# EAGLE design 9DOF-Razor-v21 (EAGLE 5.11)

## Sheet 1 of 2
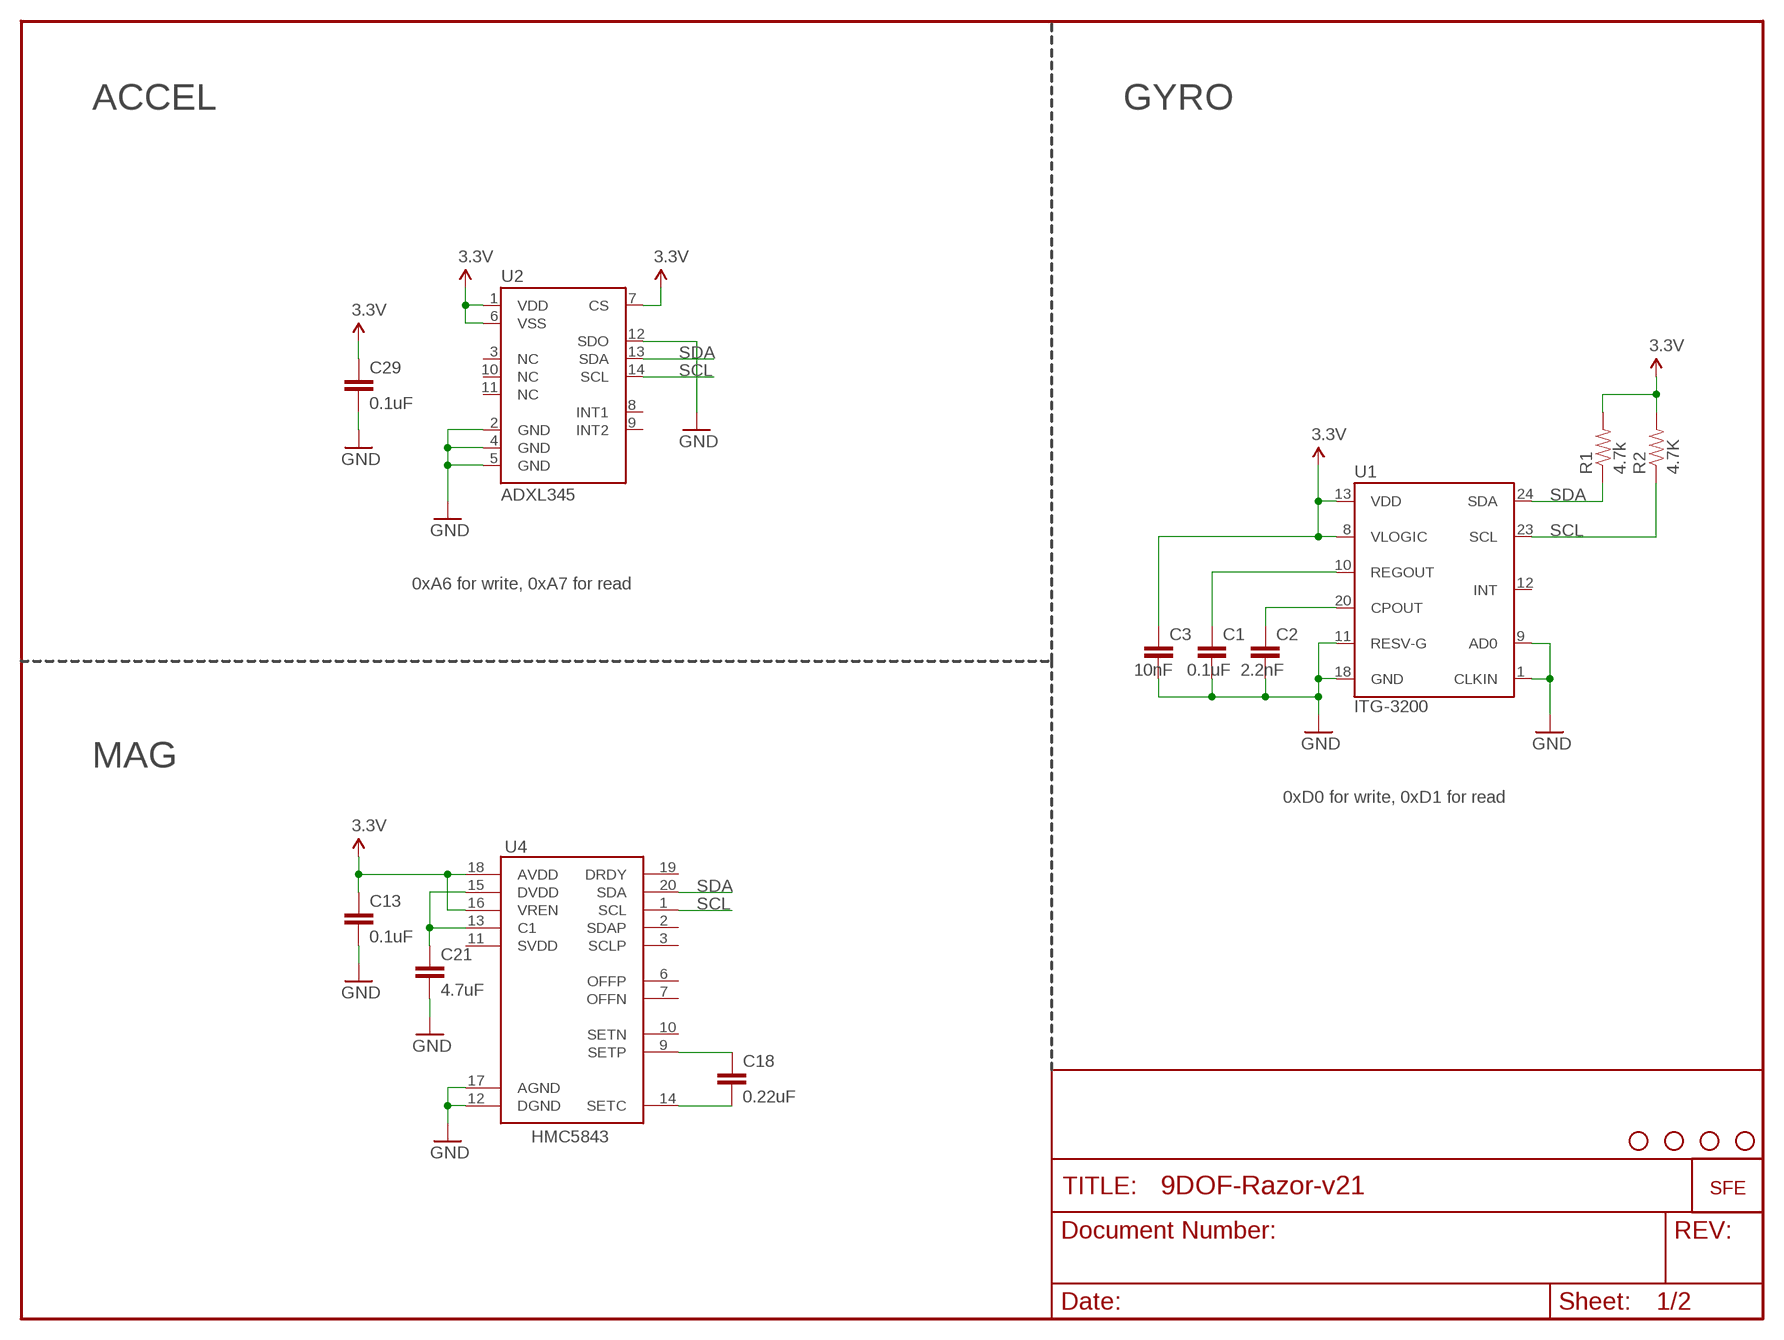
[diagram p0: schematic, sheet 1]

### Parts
C1  0.1uF  CAP0402-CAP  [0402-CAP]
C2  2.2nF  CAP0402-CAP  [0402-CAP]
C3  10nF  CAP0402-CAP  [0402-CAP]
C13  0.1uF  CAP0402-CAP  [0402-CAP]
C18  0.22uF  CAP0402-CAP  [0402-CAP]
C21  4.7uF  CAP0402-CAP  [0402-CAP]
C29  0.1uF  CAP0402-CAP  [0402-CAP]
JP2  STAND-OFF  [STAND-OFF]
JP3  LOGO-SFENEW  [SFE-NEW-WEBLOGO]
JP4  STAND-OFF  [STAND-OFF]
JP5  STAND-OFF  [STAND-OFF]
JP6  STAND-OFF  [STAND-OFF]
R1  4.7k  RESISTOR0402-RES  [0402-RES]
R2  4.7K  RESISTOR0402-RES  [0402-RES]
U1  ITG-3200  [QFN-24]
U2  ADXL345  [LGA14]
U4  HMC5843  HMC5843SMD  [LPCC20]

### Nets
3.3V: C3.1 C13.1 C29.1 R1.2 R2.2 U1.8(VLOGIC) U1.13(VDD) U2.1(VDD) U2.6(VSS) U2.7(CS) U4.16(VREN) U4.18(AVDD) ; also sheet 2
GND: C1.2 C2.2 C3.2 C13.2 C21.2 C29.2 U1.1(CLKIN) U1.9(AD0) U1.11(RESV-G) U1.18(GND) U2.2(GND) U2.4(GND) U2.5(GND) U2.12(SDO) U4.12(DGND) U4.17(AGND) ; also sheet 2
N$3: C1.1 U1.10(REGOUT)
N$4: C2.1 U1.20(CPOUT)
N$5: C21.1 U4.13(C1) U4.15(DVDD)
N$7: C18.1 U4.14(SETC)
N$11: C18.2 U4.9(SETP)
SCL: R2.1 U1.23(SCL) U2.14(SCL) U4.1(SCL) ; also sheet 2
SDA: R1.1 U1.24(SDA) U2.13(SDA) U4.20(SDA) ; also sheet 2
Unconnected: U1.12(INT) U2.3(NC) U2.8(INT1) U2.9(INT2) U2.10(NC) U2.11(NC) U4.2(SDAP) U4.3(SCLP) U4.6(OFFP) U4.7(OFFN) U4.10(SETN) U4.11(SVDD) U4.19(DRDY)

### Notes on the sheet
- ACCEL | GYRO
- 0xA6 for write, 0xA7 for read
- MAG
- 0xD0 for write, 0xD1 for read

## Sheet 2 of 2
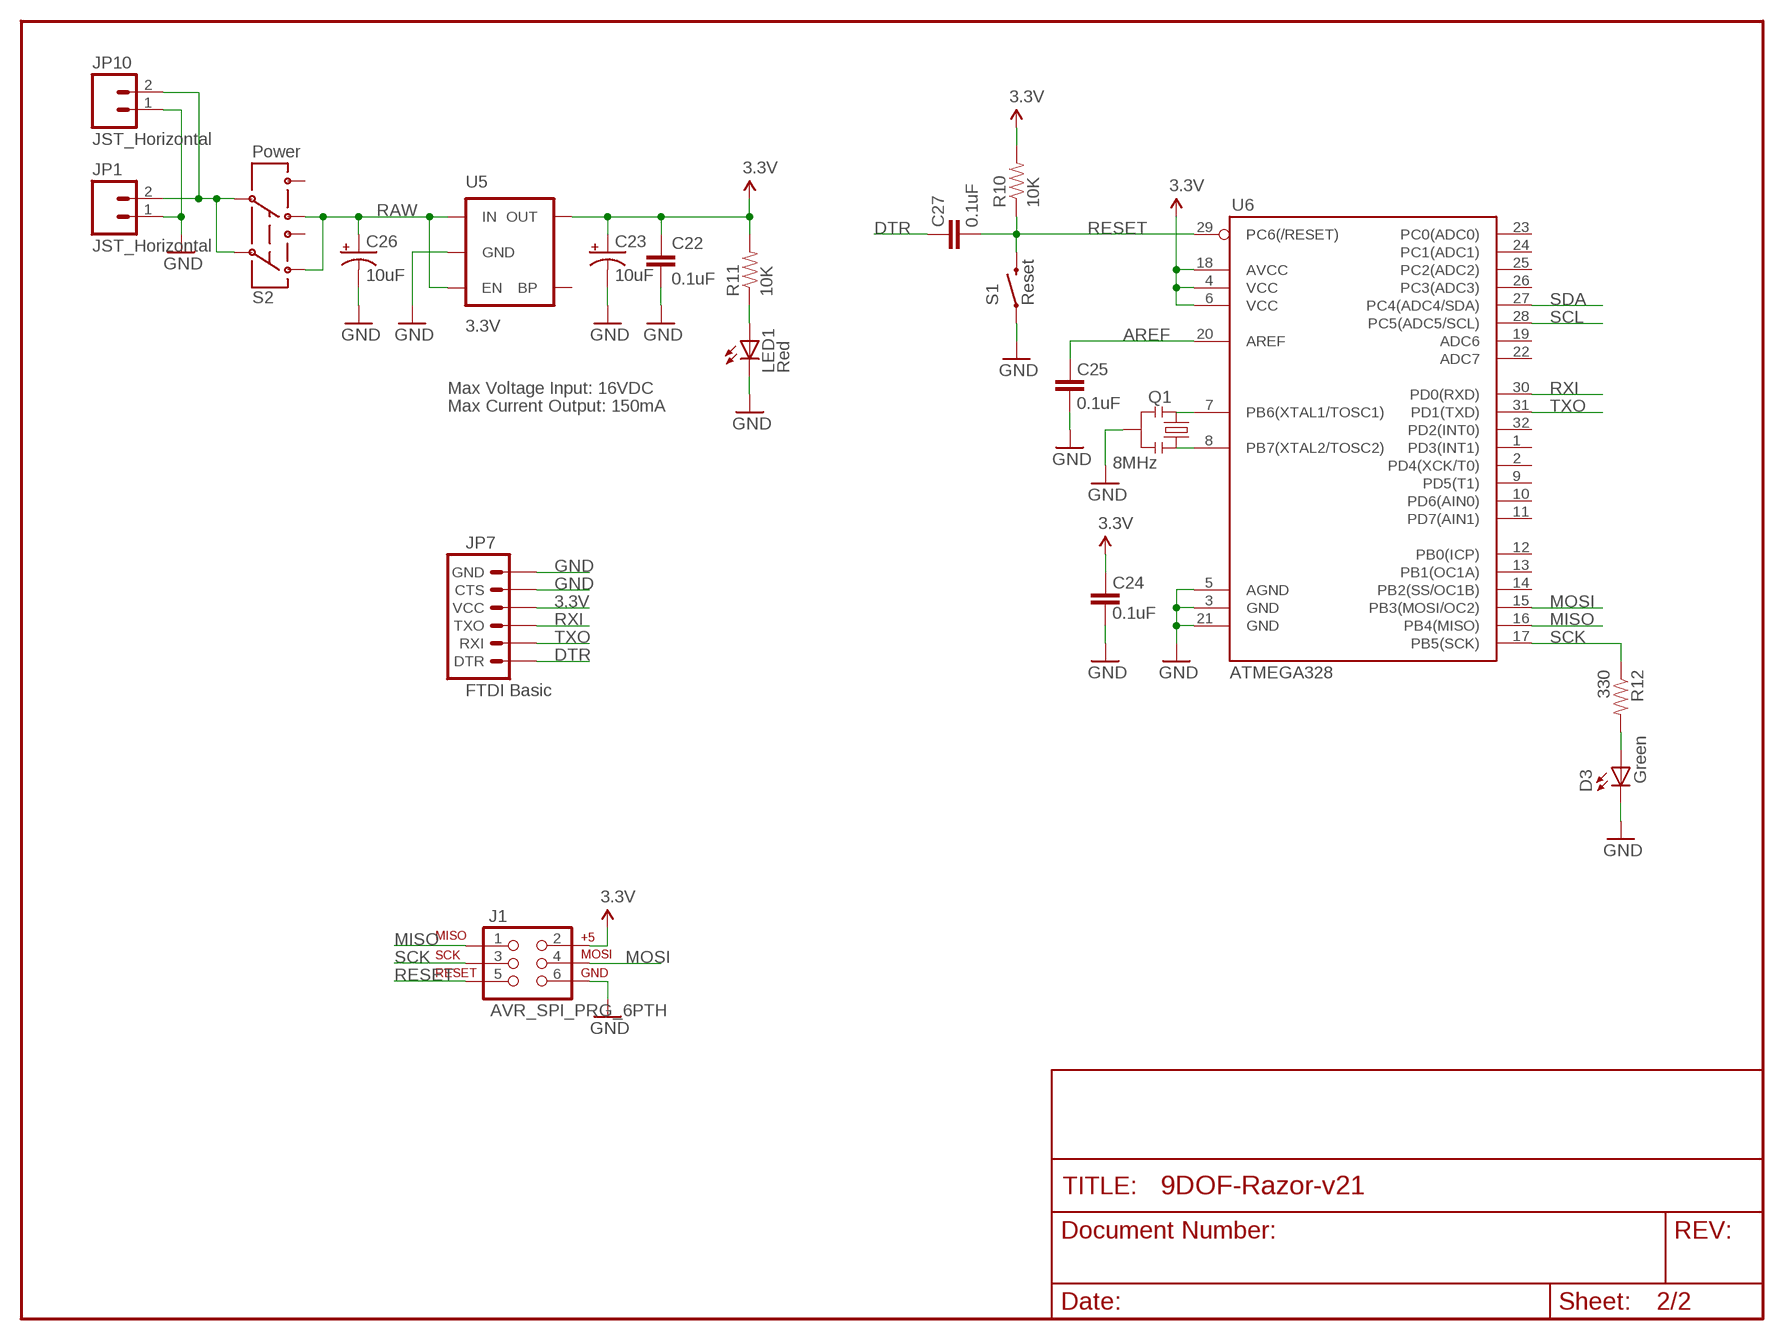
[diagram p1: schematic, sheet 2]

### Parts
C22  0.1uF  CAP0402-CAP  [0402-CAP]
C23  10uF  CAP_POL1206  [EIA3216]
C24  0.1uF  CAP0402-CAP  [0402-CAP]
C25  0.1uF  CAP0402-CAP  [0402-CAP]
C26  10uF  CAP_POL1206  [EIA3216]
C27  0.1uF  CAP0402-CAP  [0402-CAP]
D3  Green  LED0603  [LED-0603]
J1  AVR_SPI_PRG_6PTH  [2X3]
JP1  JST_Horizontal  M02-JST-2MM-SMT  [JST-2-SMD]
JP7  FTDI Basic  ARDUINO_SERIAL_PROGRAMPTH  [1X06]
JP10  JST_Horizontal  M02PTH  [1X02]
LED1  Red  LED0603  [LED-0603]
Q1  8MHz  RESONATORSMD  [RESONATOR-SMD]
R10  10K  RESISTOR0402-RES  [0402-RES]
R11  10K  RESISTOR0402-RES  [0402-RES]
R12  330  RESISTOR0402-RES  [0402-RES]
S1  Reset  SWITCH-MOMENTARY-2SMD  [TACTILE_SWITCH_SMD]
S2  Power  SWITCH-DPDTSMD  [AYZ0202]
U5  3.3V  V_REG_LDOSMD  [SOT23-5]
U6  ATMEGA328  ATMEGA168  [TQFP32-08]

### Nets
3.3V: C22.1 C23.A(+) C24.2 J1.2 JP7.4(VCC) R10.2 R11.2 U5.5(OUT) U6.4(VCC) U6.6(VCC) U6.18(AVCC) ; also sheet 1
AREF: C25.2 U6.20(AREF)
DTR: C27.2 JP7.1(DTR)
GND: C22.2 C23.C(-) C24.1 C25.1 C26.C(-) D3.C J1.6 JP1.1 JP7.5(CTS) JP7.6(GND) JP10.1 LED1.C Q1.2 S1.1 U5.2(GND) U6.3(GND) U6.5(AGND) U6.21(GND) ; also sheet 1
MISO: J1.1 U6.16(PB4(MISO))
MOSI: J1.4 U6.15(PB3(MOSI/OC2))
N$12: D3.A R12.2
N$13: Q1.1 U6.8(PB7(XTAL2/TOSC2))
N$14: Q1.3 U6.7(PB6(XTAL1/TOSC1))
N$15: JP1.2 JP10.2 S2.2 S2.5
N$38: LED1.A R11.1
RAW [vcc]: C26.A(+) S2.1 S2.4 U5.1(IN) U5.3(EN)
RESET: C27.1 J1.5 R10.1 S1.3 U6.29(PC6(/RESET))
RXI: JP7.3(TXO) U6.30(PD0(RXD))
SCK: J1.3 R12.1 U6.17(PB5(SCK))
SCL: U6.28(PC5(ADC5/SCL)) ; also sheet 1
SDA: U6.27(PC4(ADC4/SDA)) ; also sheet 1
TXO: JP7.2(RXI) U6.31(PD1(TXD))
Unconnected: S2.3 S2.6 U5.4(BP) U6.1(PD3(INT1)) U6.2(PD4(XCK/T0)) U6.9(PD5(T1)) U6.10(PD6(AIN0)) U6.11(PD7(AIN1)) U6.12(PB0(ICP)) U6.13(PB1(OC1A)) U6.14(PB2(SS/OC1B)) U6.19(ADC6) U6.22(ADC7) U6.23(PC0(ADC0)) U6.24(PC1(ADC1)) U6.25(PC2(ADC2)) U6.26(PC3(ADC3)) U6.32(PD2(INT0))

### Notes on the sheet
- Max Voltage Input: 16VDC
- Max Current Output: 150mA

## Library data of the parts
C1-C3 C13 C18 C21 C22 C24 C25 C27 C29 = SparkFun:CAP: Capacitor
C23 C26 = SparkFun:CAP_POL: Capacitor Polarized
D3 LED1 = SparkFun:LED: LEDs
J1 = SparkFun:AVR_SPI_PRG_6: AVR ISP 6 Pin This is the reduced ISP connector for AVR programming. Common on Arduino. This footprint will take up less PCB space and can be used with a 10-pin to 6-pin adapter such as SKU: BOB-08508
JP1 JP10 = SparkFun:M02: Header 2
JP2 JP4-JP6 = SparkFun:STAND-OFF: Stand Off
JP3 = SparkFun:LOGO-SFE: Spark Fun Electronics PCB Logo
JP7 = SparkFun:ARDUINO_SERIAL_PROGRAM
Q1 = SparkFun:RESONATOR: Resonator Small SMD resonator. This is the itty bitty 10/20MHz resonators with built in caps. CSTCE10M0G55 and CSTCE20M0V53. Footprint has been reviewed closely but hasn't been tested yet.
R1 R2 R10-R12 = SparkFun:RESISTOR: Resistor
S1 = SparkFun:SWITCH-MOMENTARY-2
S2 = SparkFun:SWITCH-DPDT: DPDT Version of the COM-00597
U1 = SparkFun:ITG-3200: ITG-3200 3-axis gyro, digital output, qfn24 package
U2 = SparkFun:ADXL345
U4 = SparkFun:HMC5843
U5 = SparkFun:V_REG_LDO: Voltage Regulator LDO Standard 150mA LDO voltage regulator in SOT-23 layout. Micrel part MIC5205. BP (by-pass) pin is used to lower output noise with 470pF cap.
U6 = SparkFun:ATMEGA168

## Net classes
1 vcc: width 0.254 mm

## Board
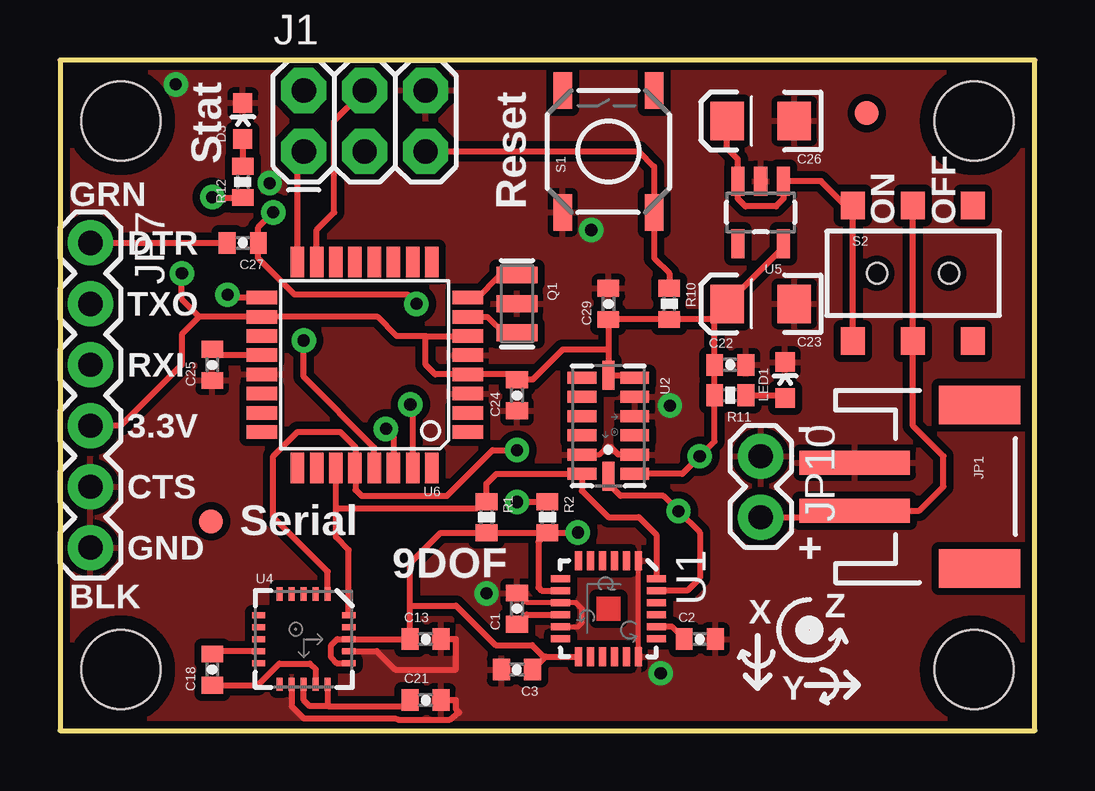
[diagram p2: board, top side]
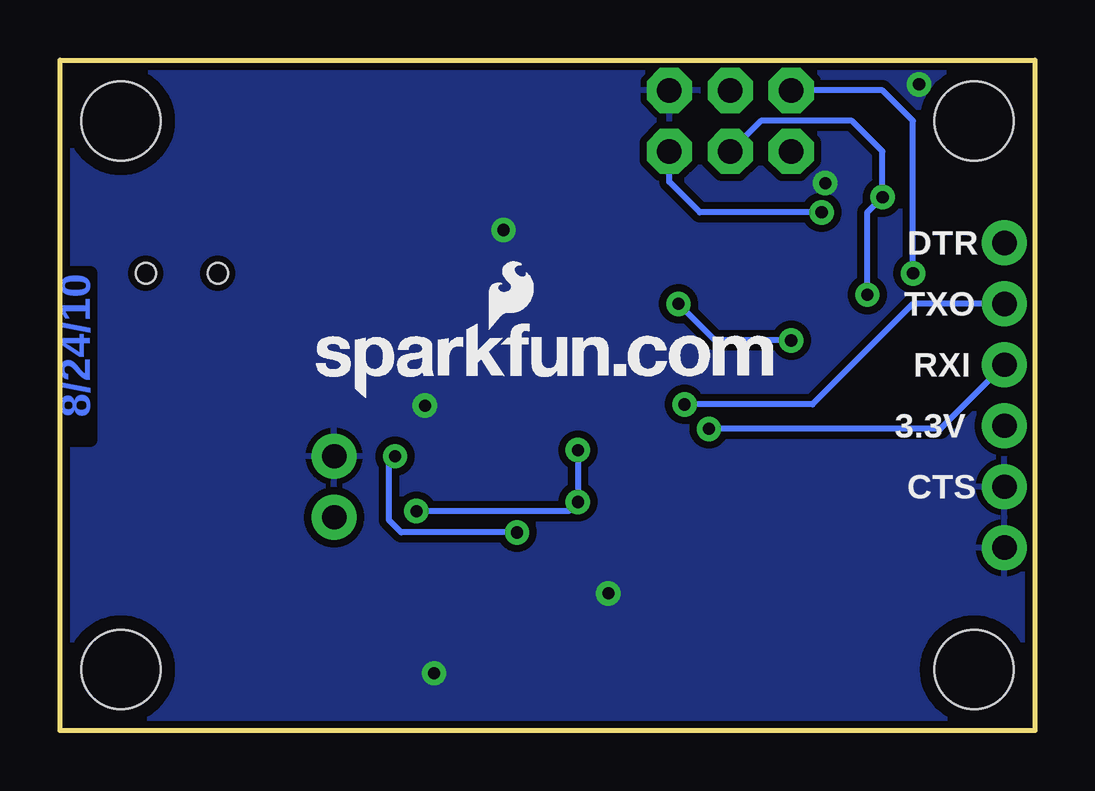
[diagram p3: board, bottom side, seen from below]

Size 40.64 x 27.94 mm. Coordinates in mm from the lower left corner, seen from the top.
Outline: 0,0 40.64,0 40.64,27.94 0,27.94 0,0
Copper layers (1*16): Top 0.035mm / dielectric 1.5mm / Bottom 0.035mm
Design rules "SparkFun": minimum track width 8mil, minimum drill 20mil, track to track 8mil, track to pad 8mil, pad to pad 8mil, via to via 8mil, smd to smd 8mil, copper to edge 8mil, drill to drill 8mil, minimum pad ring 12mil, minimum via ring 10mil, stop-mask expansion 4mil, vias tented up to drill 20mil, thermal gap 10mil

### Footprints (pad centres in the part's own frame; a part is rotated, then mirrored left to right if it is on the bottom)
0402-CAP = smd 0.7 x 0.9: 1 -0.65,0; 2 0.65,0
EIA3216 = smd 1.4 x 1.6: A 1.4,0; C -1.4,0
LED-0603 = smd 0.8 x 0.8: A 0,-0.75; C 0,0.75
2X3 = drill 1.016 pad 1.88 octagon: 1 0,0; 2 0,2.54; 3 2.54,0; 4 2.54,2.54; 5 5.08,0; 6 5.08,2.54
JST-2-SMD = smd 1 x 4.6: 1 -1,-3.7; 2 1,-3.7 | smd 1.6 x 3.4: NC1 -3.4,1.5; NC2 3.4,1.5
STAND-OFF = hole 3.302: 0,0
1X06 = drill 1.016 pad 1.88 round: 1 0,0; 2 2.54,0; 3 5.08,0; 4 7.62,0; 5 10.16,0; 6 12.7,0
FIDUCIAL-1X2 = smd 1 x 1: 1 0,0
1X02 = drill 1.016 pad 1.88 round: 1 0,0; 2 2.54,0
RESONATOR-SMD = smd 0.7 x 1.7: 1 -1.2,0; 2 0,0; 3 1.2,0
0402-RES = smd 0.7 x 0.9: 1 -0.65,0; 2 0.65,0
TACTILE_SWITCH_SMD = smd 1.524 x 0.762: 1 -2.54,1.905; 2 2.54,1.905; 3 -2.54,-1.905; 4 2.54,-1.905
AYZ0202 = smd 1 x 1.15: 1 -2.5,2.825; 2 0,2.825; 3 2.5,2.825; 4 -2.5,-2.825; 5 0,-2.825; 6 2.5,-2.825 | hole 0.85: 1.5,0; -1.5,0
QFN-24 = smd 0.8 x 0.3: 1 -2,1.25; 2 -2,0.75; 3 -2,0.25; 4 -2,-0.25; 5 -2,-0.75; 6 -2,-1.25; 13 2,-1.25; 14 2,-0.75; 15 2,-0.25; 16 2,0.25; 17 2,0.75; 18 2,1.25 | smd 0.3 x 0.8: 7 -1.25,-2; 8 -0.75,-2; 9 -0.25,-2; 10 0.25,-2; 11 0.75,-2; 12 1.25,-2; 19 1.25,2; 20 0.75,2; 21 0.25,2; 22 -0.25,2; 23 -0.75,2; 24 -1.25,2
LGA14 = smd 0.5 x 1.2: 1 2,1.1; 2 1.2,1.1; 3 0.4,1.1; 4 -0.4,1.1; 5 -1.2,1.1; 6 -2,1.1; 8 -2,-1.1; 9 -1.2,-1.1; 10 -0.4,-1.1; 11 0.4,-1.1; 12 1.2,-1.1; 13 2,-1.1 | smd 1.2 x 0.5: 7 -2.1,0; 14 2.1,0
LPCC20 = smd 0.25 x 0.56: 1 1,1.88; 2 0.5,1.88; 3 0,1.88; 4 -0.5,1.88; 5 -1,1.88; 11 -1,-1.88; 12 -0.5,-1.88; 13 0,-1.88; 14 0.5,-1.88; 15 1,-1.88 | smd 0.56 x 0.25: 6 -1.88,1; 7 -1.88,0.5; 8 -1.88,0; 9 -1.88,-0.5; 10 -1.88,-1; 16 1.88,-1; 17 1.88,-0.5; 18 1.88,0; 19 1.88,0.5; 20 1.88,1
SOT23-5 = smd 0.55 x 1.2: 1 -0.95,-1.3; 2 0,-1.3; 3 0.95,-1.3; 4 0.95,1.3; 5 -0.95,1.3
TQFP32-08 = smd 1.27 x 0.559: 1 -4.293,2.8; 2 -4.293,2; 3 -4.293,1.2; 4 -4.293,0.4; 5 -4.293,-0.4; 6 -4.293,-1.2; 7 -4.293,-2; 8 -4.293,-2.8; 17 4.293,-2.8; 18 4.293,-2; 19 4.293,-1.2; 20 4.293,-0.4; 21 4.293,0.4; 22 4.293,1.2; 23 4.293,2; 24 4.293,2.8 | smd 0.559 x 1.27: 9 -2.8,-4.293; 10 -2,-4.293; 11 -1.2,-4.293; 12 -0.4,-4.293; 13 0.4,-4.293; 14 1.2,-4.293; 15 2,-4.293; 16 2.8,-4.293; 25 2.8,4.293; 26 2,4.293; 27 1.2,4.293; 28 0.4,4.293; 29 -0.4,4.293; 30 -1.2,4.293; 31 -2,4.293; 32 -2.8,4.293

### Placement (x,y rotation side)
C1  19.05,5.08 90 top
C2  26.67,3.81 0 top
C3  19.05,2.54 180 top
C13  15.24,3.81 0 top
C18  6.35,2.54 90 top
C21  15.24,1.27 0 top
C22  27.94,15.24 0 top
C23  29.21,17.78 180 top
C24  19.05,13.97 90 top
C25  6.35,15.24 90 top
C26  29.21,25.4 180 top
C27  7.62,20.32 180 top
C29  22.86,17.78 90 top
D3  7.62,25.4 0 top
J1  10.16,24.13 0 top
JP1  36.83,10.16 270 top
JP2  2.54,25.4 90 top
JP3  29.97,13.84 0 bottom
JP4  2.54,2.54 90 top
JP5  38.1,25.4 90 top
JP6  38.1,2.54 90 top
JP7  1.27,20.32 270 top
JP8  FIDUCIAL1X2  [FIDUCIAL-1X2]  6.3,8.71 0 top
JP9  FIDUCIAL1X2  [FIDUCIAL-1X2]  33.63,25.73 0 top
JP10  29.21,11.43 270 top
LED1  30.23,14.61 0 top
Q1  19.05,17.78 270 top
R1  17.78,8.89 270 top
R2  20.32,8.89 270 top
R10  25.4,17.78 270 top
R11  27.94,13.97 180 top
R12  7.62,22.86 90 top
S1  22.86,24.13 90 top
S2  35.56,19.05 0 top
U1  22.86,5.08 270 top
U2  22.86,12.7 270 top
U4  10.16,3.81 0 top
U5  29.21,21.59 180 top
U6  12.7,15.24 180 top

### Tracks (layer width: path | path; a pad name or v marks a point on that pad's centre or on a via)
3.3V  (via drill 0.51)
  Top 0.254: JP7.4 2.54,12.7 5.08,15.24 5.08,16.51 5.81,17.24 | 5.81,17.24 U6.18 13.24,17.24 14.04,16.44 15.24,16.44 | 15.24,16.44 U6.6 | 15.24,16.44 15.24,15.24 15.64,14.84 U6.4 18.83,14.84 C24.2 19.7,14.62 20.95,15.88 22.86,15.88 | 22.86,15.88 U2.7 23.86,14.8 U2.6 | 22.86,15.88 C29.1 R10.2 27.16,17.13 | 27.16,17.13 C23.A 30.16,20.13 U5.5 | 27.16,17.13 27.29,17 C22.1 R11.2 27.29,12.05 v26.67,11.43 25.94,10.7 U2.1 | v5.08,19.05 5.08,17.97 5.81,17.24 | U4.16 11.54,2.81 11.3,3.05 11.3,3.56 11.56,3.81 U4.18 C13.1 14.59,5.21 | R2.2 R1.2 15.86,8.24 14.59,6.97 14.59,5.21 | 20.24,3.08 U1.13 | 20.24,3.08 C3.1 | U1.8 20.08,5.83 19.94,5.97 19.94,7.86 R2.2 | 20.24,3.08 20.16,3.08 19.68,3.56 18.16,3.56 16.51,5.21 14.59,5.21 | R2.2 21.57,8.24 v21.59,8.26
  Bottom 0.254: J1.2 6.35,26.67 5.08,25.4 v5.08,19.05 | v21.59,8.26 26.42,8.26 26.92,8.76 26.92,11.18 v26.67,11.43
AREF
  Top 0.254: U6.20 6.6,15.64 C25.2
DTR
  Top 0.254: JP7.1 C27.2
GND  (via drill 0.51)
  Top 0.203: U2.12 22.5,11.5 22.86,11.86 | U1.18 U1.1 | C1.2 19.45,5.33 U1.9 21.52,5.33 21.77,5.08 21.77,4.5 21.6,4.33 U1.11
  Top 0.254: U4.17 13.2,3.31 13.97,2.54 16.51,2.54 16.51,3.81 C13.2 | C21.2 16.51,1.27 16.51,0.89 16.64,0.76 16.26,0.46 14.1,0.46 13.97,0.51 10.16,0.51 9.66,1.01 U4.12 | U2.2 23.27,11.5 22.96,11.81
  other vias: 4.83,26.92 17.78,5.71 25.04,2.39 25.43,13.54 22.15,20.85 8.74,22.81
  pour Bottom (isolate 0.305): 0,27.94 0,0 40.64,0 40.64,27.94
  pour Top (isolate 0.305): 0,27.94 40.64,27.94 40.64,0 0,0
MISO
  Top 0.254: U6.16 9.9,23.87 J1.1
MOSI
  Top 0.254: U6.15 10.7,20.86 11.43,21.59 11.43,25.4 J1.4
N$3
  Top 0.254: U1.10 19.45,4.83 C1.1
N$4
  Top 0.254: U1.20 25.5,4.33 C2.1
N$5
  Top 0.254: U4.13 10.16,1.27 10.41,1.02 11.18,1.02 | 11.18,1.02 14.34,1.02 C21.1 | U4.15 11.16,1.03 11.18,1.02
N$7
  Top 0.254: U4.14 10.66,2.55 10.41,2.79 9.14,2.79 8.24,1.89 C18.1
N$11
  Top 0.254: U4.9 6.47,3.31 C18.2
N$12
  Top 0.254: D3.A R12.2
N$13
  Top 0.254: U6.8 17.41,18.04 18.29,18.92 18.99,18.92 Q1.1
N$14
  Top 0.254: U6.7 17.81,17.24 18.54,16.51 18.98,16.51 Q1.3
N$15
  Top 0.254: S2.2 S2.5 35.56,12.7 36.83,11.43 36.83,10.16 35.83,9.16 JP1.2 32.86,8.89 JP10.2
N$38
  Top 0.254: R11.1 30.11,13.97 LED1.A
RAW
  Top 0.254: C26.A 27.81,24.26 28.26,23.81 U5.3 28.26,22.16 28.58,21.84 29.84,21.84 30.16,22.16 U5.1 31.72,22.89 32.73,21.88 S2.1 S2.4
RESET  (via drill 0.51)
  Top 0.254: R10.1 25.4,19.05 24.77,19.68 S1.3 24.77,23.5 24.13,24.13 J1.5 | v8.89,21.59 8.27,20.97 C27.1 8.27,19.67 9.78,18.16 14.48,18.16 v14.86,17.78 | U6.29 13.1,11.79 10.16,14.73 v10.16,16.26
  Bottom 0.254: v8.89,21.59 13.97,21.59 15.24,22.86 J1.5 | v10.16,16.26 13.34,16.26 v14.86,17.78
RXI  (via drill 0.51)
  Top 0.254: U6.30 13.9,12.26 v13.59,12.57
  Bottom 0.254: v13.59,12.57 3.94,12.57 JP7.3
SCK  (via drill 0.51)
  Top 0.254: R12.1 6.37,22.21 v6.35,22.23 | U6.17 7.11,18.04 v6.98,18.16
  Bottom 0.254: J1.3 11.43,25.4 7.62,25.4 6.35,24.13 v6.35,22.23 6.98,21.59 v6.98,18.16
SCL  (via drill 0.51)
  Top 0.254: U4.1 11.16,6.62 8.89,8.89 8.89,11.43 9.91,12.45 11.68,12.45 12.32,11.81 12.32,10.97 | 12.32,10.97 U6.28 | U1.23 26.15,5.83 26.67,6.35 26.67,8.26 v25.78,9.14 25.15,9.78 23.37,9.78 22.86,10.29 U2.14 | 12.32,10.97 12.32,10.03 12.57,9.78 16.13,9.78 18.03,11.68 v19.05,11.68 | R2.1 19.06,9.54 v19.05,9.53
  Bottom 0.254: v19.05,11.68 v19.05,9.53 19.43,9.14 v25.78,9.14
SDA
  Top 0.254: U4.20 12.04,7.52 11.5,8.06 11.5,9.27 | 11.5,9.27 U6.27 | U1.24 24.86,8.16 24.13,8.89 22.86,8.89 21.76,9.99 U2.13 18.19,10.7 17.78,10.29 R1.1 17.67,9.54 17.4,9.27 11.5,9.27
TXO  (via drill 0.51)
  Top 0.254: U6.31 14.7,13.49 v14.61,13.59
  Bottom 0.254: JP7.2 5.08,17.78 9.27,13.59 v14.61,13.59

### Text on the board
Bottom: 8/24/10
tPlace: Stat | GRN | Reset | ON | OFF | DTR | TXO | RXI | 3.3V | - | CTS | Serial | GND | + | 9DOF | BLK | Z | X | Y
bPlace: DTR | TXO | RXI | 3.3V | CTS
